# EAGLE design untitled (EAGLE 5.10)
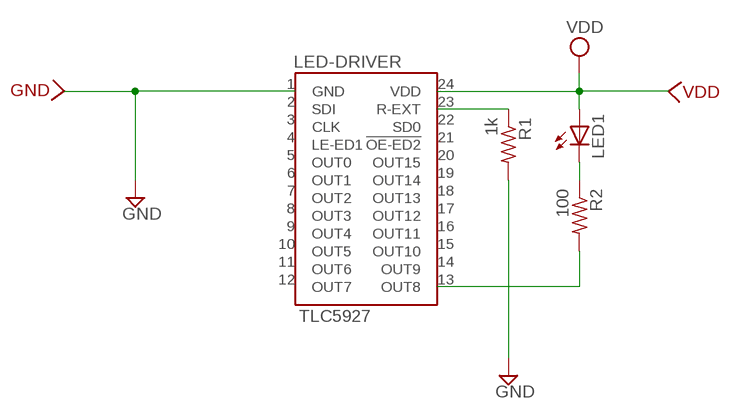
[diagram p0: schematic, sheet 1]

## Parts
GND  WIREPAD-SMD-SMALL-NAMED  [WIREPAD-SMD-SMALL]
LED1  LED-SMD-RED  [LED-SMD-RED]
LED-DRIVER  TLC5927  [SO24W]
R1  1k  R-US_M1206  [M1206]
R2  100  R-US_M1206  [M1206]
VDD  WIREPAD-SMD-SMALL-NAMED  [WIREPAD-SMD-SMALL]

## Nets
GND: GND.1 LED-DRIVER.1(GND) R1.2
N$1: LED-DRIVER.23(R-EXT) R1.1
N$2: LED1.CATHODE(C) R2.1
N$3: LED-DRIVER.13(OUT8) R2.2
VDD: LED1.ANODE(A) LED-DRIVER.24(VDD) VDD.1
Unconnected: LED-DRIVER.2(SDI) LED-DRIVER.3(CLK) LED-DRIVER.4(LE-ED1) LED-DRIVER.5(OUT0) LED-DRIVER.6(OUT1) LED-DRIVER.7(OUT2) LED-DRIVER.8(OUT3) LED-DRIVER.9(OUT4) LED-DRIVER.10(OUT5) LED-DRIVER.11(OUT6) LED-DRIVER.12(OUT7) LED-DRIVER.14(OUT9) LED-DRIVER.15(OUT10) LED-DRIVER.16(OUT11) LED-DRIVER.17(OUT12) LED-DRIVER.18(OUT13) LED-DRIVER.19(OUT14) LED-DRIVER.20(OUT15) LED-DRIVER.21(!OE-ED2) LED-DRIVER.22(SD0)

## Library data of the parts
GND VDD = trl:WIREPAD-SMD-SMALL-NAMED
LED1 = trl:LED-SMD-RED
LED-DRIVER = trl:TLC5927
R1 R2 = resistor:R-US_: RESISTOR, American symbol

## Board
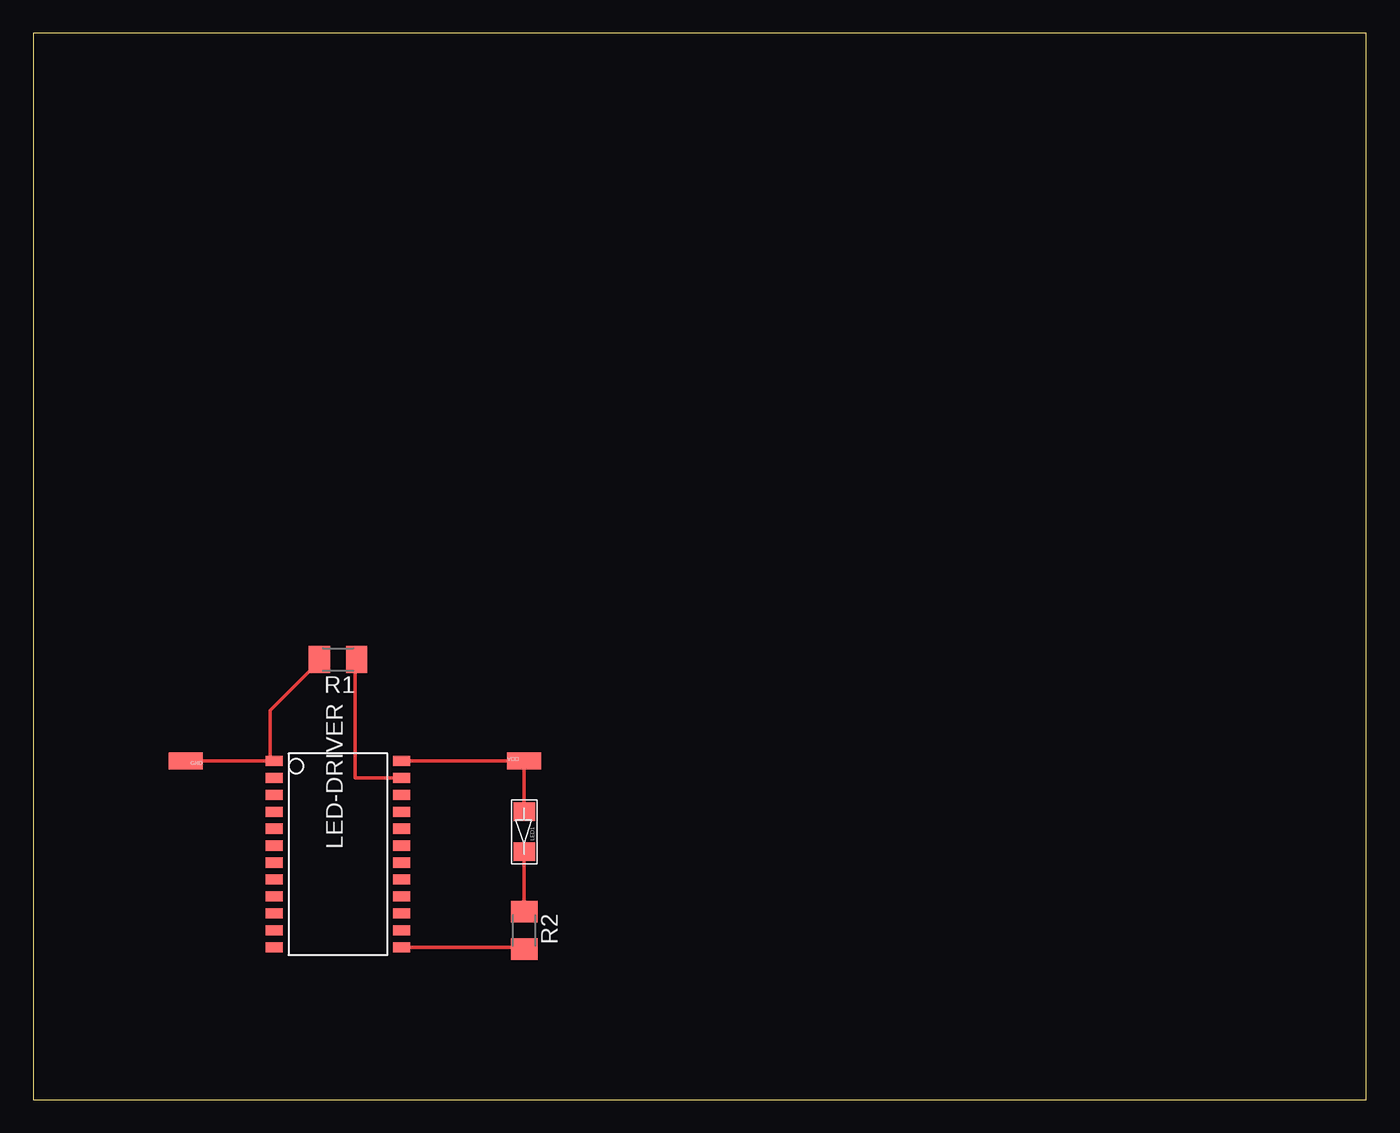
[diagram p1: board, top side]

Size 100 x 80 mm. Coordinates in mm from the lower left corner, seen from the top.
Outline: 0,0 100,0 100,80 0,80 0,0
Copper layers (1*16): Top 0.035mm / dielectric 1.5mm / Bottom 0.035mm
Design rules "default": minimum track width 10mil, minimum drill 24mil, track to track 8mil, track to pad 8mil, pad to pad 8mil, via to via 8mil, smd to smd 8mil, copper to edge 40mil, drill to drill 8mil, minimum pad ring 10mil, minimum via ring 8mil, stop-mask expansion 4mil, vias tented up to drill 0mil, thermal gap 10mil

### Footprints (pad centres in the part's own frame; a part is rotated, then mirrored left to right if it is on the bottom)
WIREPAD-SMD-SMALL = smd 2.54 x 1.27: 1 0,0
LED-SMD-RED = smd 1.4 x 1.6: ANODE 0,0; CATHODE 3,0
SO24W = smd 0.762 x 1.27: 1 -7.62,-4.78; 2 -6.35,-4.78; 3 -5.08,-4.78; 4 -3.81,-4.78; 5 -2.54,-4.78; 6 -1.27,-4.78; 7 0,-4.78; 8 1.27,-4.78; 9 2.54,-4.78; 10 3.81,-4.78; 11 5.08,-4.78; 12 6.35,-4.78; 13 6.35,4.78; 14 5.08,4.78; 15 3.81,4.78; 16 2.54,4.78; 17 1.27,4.78; 18 0,4.78; 19 -1.27,4.78; 20 -2.54,4.78; 21 -3.81,4.78; 22 -5.08,4.78; 23 -6.35,4.78; 24 -7.62,4.78
M1206 = smd 1.6 x 2: 1 -1.4,0; 2 1.4,0

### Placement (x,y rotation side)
GND  11.43,25.4 180 top
LED1  36.83,21.59 270 top
LED-DRIVER  22.86,17.78 270 top
R1  22.86,33.02 180 top
R2  36.83,12.7 270 top
VDD  36.83,25.4 0 top

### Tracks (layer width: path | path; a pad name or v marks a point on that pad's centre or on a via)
GND
  Top 0.254: GND.1 17.78,25.4 | 17.78,25.4 LED-DRIVER.1 17.78,25.4 | 17.78,25.4 17.78,29.21 21.59,33.02 R1.2
N$1
  Top 0.254: LED-DRIVER.23 24.13,24.13 24.13,33.02 R1.1 | LED-DRIVER.23 27.94,24.13 LED-DRIVER.23
N$2
  Top 0.254: R2.1 36.83,13.97 R2.1 | R2.1 LED1.CATHODE | LED1.CATHODE 36.83,19.05 LED1.CATHODE
N$3
  Top 0.254: LED-DRIVER.13 27.94,11.43 36.83,11.43 R2.2
VDD
  Top 0.254: LED-DRIVER.24 27.94,25.4 VDD.1 LED1.ANODE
